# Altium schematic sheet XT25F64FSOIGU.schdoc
size 127 x 101 mm
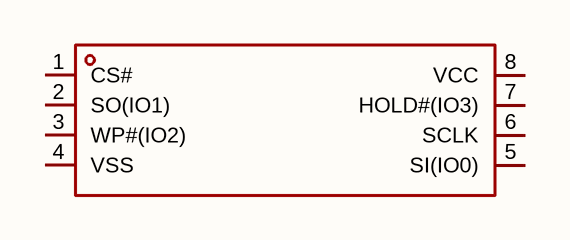
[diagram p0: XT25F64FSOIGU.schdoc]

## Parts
U?  xt25f64fsoigu  [SOP-8_L4.9-W3.9-P1.27-LS6.0-BL]  (value not drawn)

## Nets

Not connected (* = marked no-connect by the designer): U? 1(CS#) 2(SO(IO1)) 3(WP#(IO2)) 4(VSS) 5(SI(IO0)) 6(SCLK) 7(HOLD#(IO3)) 8(VCC)

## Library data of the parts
U? = xt25f64fsoigu: 接口类型:SPI;存储容量:64Mbit;时钟频率(fc):133MHz;; Manufacturer: XTX(芯天下); AddInBom: yes; ModelId: 75c24a7891ee4dd6bdac16a7163ff87e; ModelName: SOP-8_L4.9-W3.9-P1.27-LS6.0-BL-1; ModelTransform: 192.913,236.22,0,0,0,0,-0.393,2.749,0; Interface: SPI; Memory Size: 64Mbit; Clock Frequency: 133MHz; Voltage - Supply: 2.7V~3.6V; Standby Supply Current: 0.3uA; Program / Erase Cycles: 100000次; Page Programming Time (Tpp): 400us; Block Erase Time(tBE): 300ms@(64KB); Data Retention - TDR (Year): 20年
